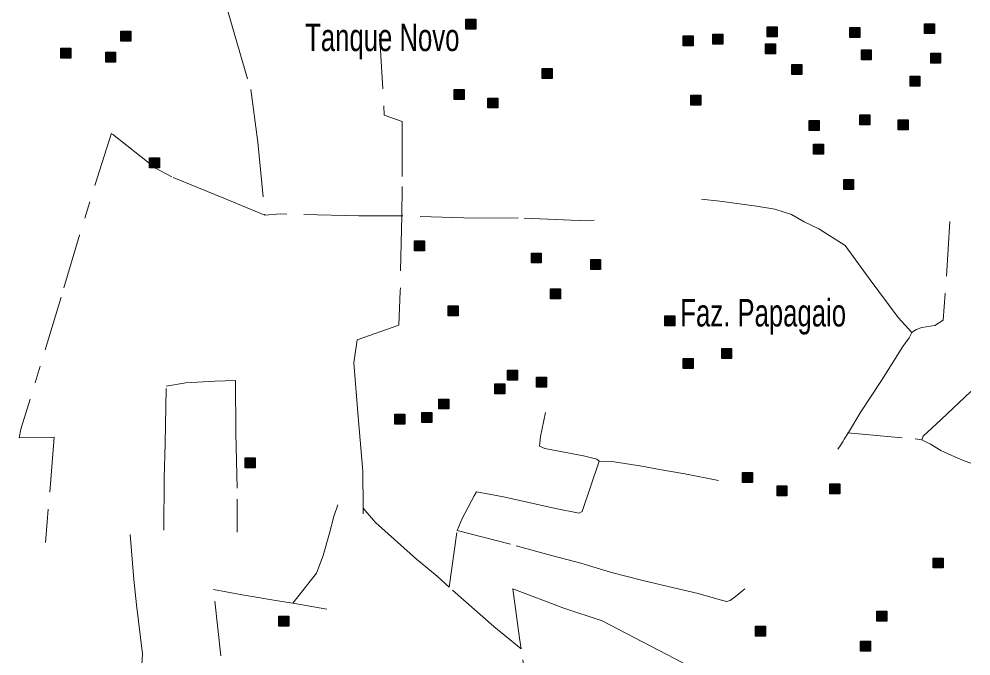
# Model space of a CAD drawing. Extents: x 445.4 to 500, y 8728.7 to 8784.
# Drawn here: x 494.45 to 500, y 8730.77 to 8734.48 of the extents above; entities that cross this region are included whole.
import ezdxf
from ezdxf.enums import TextEntityAlignment as Align

# ---------------------------------------------------------------- set-up
doc = ezdxf.new("R2010")
doc.units = 0
doc.header["$LTSCALE"] = 0.064
doc.linetypes.add('DOT_DASHED', pattern=[7.7, 5, -1.2, 0.3, -1.2])
doc.layers.add('2', color=7, linetype='Continuous', lineweight=25)
doc.layers.add('22', color=7, linetype='DOT_DASHED', lineweight=13)
doc.layers.add('61', color=7, linetype='Continuous')

msp = doc.modelspace()

# ---------------------------------------------------------------- hatches: boundary and pattern name
at = {"layer": '2'}
for points in [[(497.0563, 8734.475), (497.1143, 8734.475), (497.1143, 8734.417), (497.0563, 8734.417)], [(498.8131, 8734.4308), (498.8711, 8734.4308), (498.8711, 8734.3728), (498.8131, 8734.3728)], [(499.7287, 8734.449), (499.7867, 8734.449), (499.7867, 8734.391), (499.7287, 8734.391)], [(495.0456, 8734.4055), (495.1036, 8734.4055), (495.1036, 8734.3475), (495.0456, 8734.3475)], [(498.323, 8734.3781), (498.381, 8734.3781), (498.381, 8734.3201), (498.323, 8734.3201)], [(498.4961, 8734.3877), (498.5541, 8734.3877), (498.5541, 8734.3297), (498.4961, 8734.3297)], [(499.2946, 8734.4271), (499.3526, 8734.4271), (499.3526, 8734.3691), (499.2946, 8734.3691)], [(498.8021, 8734.3322), (498.8601, 8734.3322), (498.8601, 8734.2742), (498.8021, 8734.2742)], [(494.6956, 8734.3068), (494.7536, 8734.3068), (494.7536, 8734.2488), (494.6956, 8734.2488)], [(494.9569, 8734.2822), (495.0149, 8734.2822), (495.0149, 8734.2242), (494.9569, 8734.2242)], [(499.3612, 8734.2957), (499.4192, 8734.2957), (499.4192, 8734.2377), (499.3612, 8734.2377)], [(499.7652, 8734.2774), (499.8232, 8734.2774), (499.8232, 8734.2194), (499.7652, 8734.2194)], [(498.9553, 8734.2118), (499.0133, 8734.2118), (499.0133, 8734.1538), (498.9553, 8734.1538)], [(497.5004, 8734.1885), (497.5584, 8734.1885), (497.5584, 8734.1305), (497.5004, 8734.1305)], [(499.6448, 8734.1424), (499.7028, 8734.1424), (499.7028, 8734.0844), (499.6448, 8734.0844)], [(496.9878, 8734.0652), (497.0458, 8734.0652), (497.0458, 8734.0072), (496.9878, 8734.0072)], [(497.1849, 8734.0159), (497.2429, 8734.0159), (497.2429, 8733.9579), (497.1849, 8733.9579)], [(498.3679, 8734.0327), (498.4259, 8734.0327), (498.4259, 8733.9747), (498.3679, 8733.9747)], [(499.0575, 8733.8854), (499.1155, 8733.8854), (499.1155, 8733.8274), (499.0575, 8733.8274)], [(499.3529, 8733.9183), (499.4109, 8733.9183), (499.4109, 8733.8603), (499.3529, 8733.8603)], [(499.5755, 8733.8891), (499.6335, 8733.8891), (499.6335, 8733.8311), (499.5755, 8733.8311)], [(499.083, 8733.7477), (499.141, 8733.7477), (499.141, 8733.6897), (499.083, 8733.6897)], [(495.2132, 8733.6677), (495.2712, 8733.6677), (495.2712, 8733.6097), (495.2132, 8733.6097)], [(499.2581, 8733.5416), (499.3161, 8733.5416), (499.3161, 8733.4836), (499.2581, 8733.4836)], [(496.7561, 8733.1844), (496.8141, 8733.1844), (496.8141, 8733.1264), (496.7561, 8733.1264)], [(497.4378, 8733.1128), (497.4958, 8733.1128), (497.4958, 8733.0548), (497.4378, 8733.0548)], [(497.7836, 8733.0747), (497.8416, 8733.0747), (497.8416, 8733.0167), (497.7836, 8733.0167)], [(497.5497, 8732.9033), (497.6077, 8732.9033), (497.6077, 8732.8453), (497.5497, 8732.8453)], [(496.9532, 8732.8047), (497.0112, 8732.8047), (497.0112, 8732.7467), (496.9532, 8732.7467)], [(498.2167, 8732.7469), (498.2747, 8732.7469), (498.2747, 8732.6889), (498.2167, 8732.6889)], [(498.5472, 8732.5563), (498.6052, 8732.5563), (498.6052, 8732.4983), (498.5472, 8732.4983)], [(498.3236, 8732.4989), (498.3816, 8732.4989), (498.3816, 8732.4409), (498.3236, 8732.4409)], [(497.2983, 8732.4299), (497.3563, 8732.4299), (497.3563, 8732.3719), (497.2983, 8732.3719)], [(497.4682, 8732.3886), (497.5262, 8732.3886), (497.5262, 8732.3306), (497.4682, 8732.3306)], [(497.2244, 8732.3509), (497.2824, 8732.3509), (497.2824, 8732.2929), (497.2244, 8732.2929)], [(496.899, 8732.2622), (496.957, 8732.2622), (496.957, 8732.2042), (496.899, 8732.2042)], [(496.6427, 8732.1734), (496.7007, 8732.1734), (496.7007, 8732.1154), (496.6427, 8732.1154)], [(496.7994, 8732.1828), (496.8574, 8732.1828), (496.8574, 8732.1248), (496.7994, 8732.1248)], [(495.7702, 8731.919), (495.8282, 8731.919), (495.8282, 8731.861), (495.7702, 8731.861)], [(498.6686, 8731.8331), (498.7266, 8731.8331), (498.7266, 8731.7751), (498.6686, 8731.7751)], [(499.1779, 8731.7677), (499.2359, 8731.7677), (499.2359, 8731.7097), (499.1779, 8731.7097)], [(498.8698, 8731.7555), (498.9278, 8731.7555), (498.9278, 8731.6975), (498.8698, 8731.6975)], [(499.7797, 8731.3356), (499.8377, 8731.3356), (499.8377, 8731.2776), (499.7797, 8731.2776)], [(495.9668, 8730.9972), (496.0248, 8730.9972), (496.0248, 8730.9392), (495.9668, 8730.9392)], [(499.4514, 8731.0253), (499.5094, 8731.0253), (499.5094, 8730.9673), (499.4514, 8730.9673)], [(498.7438, 8730.9377), (498.8018, 8730.9377), (498.8018, 8730.8797), (498.7438, 8730.8797)], [(499.3566, 8730.8508), (499.4146, 8730.8508), (499.4146, 8730.7928), (499.3566, 8730.7928)]]:
    msp.add_hatch(color=256, dxfattribs=at).paths.add_polyline_path(points)

# ---------------------------------------------------------------- linework, layer by layer
for points in [[(497.0563, 8734.475), (497.1143, 8734.475), (497.1143, 8734.417), (497.0563, 8734.417)], [(498.8131, 8734.4308), (498.8711, 8734.4308), (498.8711, 8734.3728), (498.8131, 8734.3728)], [(499.7287, 8734.449), (499.7867, 8734.449), (499.7867, 8734.391), (499.7287, 8734.391)], [(495.0456, 8734.4055), (495.1036, 8734.4055), (495.1036, 8734.3475), (495.0456, 8734.3475)], [(498.323, 8734.3781), (498.381, 8734.3781), (498.381, 8734.3201), (498.323, 8734.3201)], [(498.4961, 8734.3877), (498.5541, 8734.3877), (498.5541, 8734.3297), (498.4961, 8734.3297)], [(499.2946, 8734.4271), (499.3526, 8734.4271), (499.3526, 8734.3691), (499.2946, 8734.3691)], [(498.8021, 8734.3322), (498.8601, 8734.3322), (498.8601, 8734.2742), (498.8021, 8734.2742)], [(494.6956, 8734.3068), (494.7536, 8734.3068), (494.7536, 8734.2488), (494.6956, 8734.2488)], [(494.9569, 8734.2822), (495.0149, 8734.2822), (495.0149, 8734.2242), (494.9569, 8734.2242)], [(499.3612, 8734.2957), (499.4192, 8734.2957), (499.4192, 8734.2377), (499.3612, 8734.2377)], [(499.7652, 8734.2774), (499.8232, 8734.2774), (499.8232, 8734.2194), (499.7652, 8734.2194)], [(498.9553, 8734.2118), (499.0133, 8734.2118), (499.0133, 8734.1538), (498.9553, 8734.1538)], [(497.5004, 8734.1885), (497.5584, 8734.1885), (497.5584, 8734.1305), (497.5004, 8734.1305)], [(499.6448, 8734.1424), (499.7028, 8734.1424), (499.7028, 8734.0844), (499.6448, 8734.0844)], [(496.9878, 8734.0652), (497.0458, 8734.0652), (497.0458, 8734.0072), (496.9878, 8734.0072)], [(497.1849, 8734.0159), (497.2429, 8734.0159), (497.2429, 8733.9579), (497.1849, 8733.9579)], [(498.3679, 8734.0327), (498.4259, 8734.0327), (498.4259, 8733.9747), (498.3679, 8733.9747)], [(499.0575, 8733.8854), (499.1155, 8733.8854), (499.1155, 8733.8274), (499.0575, 8733.8274)], [(499.3529, 8733.9183), (499.4109, 8733.9183), (499.4109, 8733.8603), (499.3529, 8733.8603)], [(499.5755, 8733.8891), (499.6335, 8733.8891), (499.6335, 8733.8311), (499.5755, 8733.8311)], [(499.083, 8733.7477), (499.141, 8733.7477), (499.141, 8733.6897), (499.083, 8733.6897)], [(495.2132, 8733.6677), (495.2712, 8733.6677), (495.2712, 8733.6097), (495.2132, 8733.6097)], [(499.2581, 8733.5416), (499.3161, 8733.5416), (499.3161, 8733.4836), (499.2581, 8733.4836)], [(496.7561, 8733.1844), (496.8141, 8733.1844), (496.8141, 8733.1264), (496.7561, 8733.1264)], [(497.4378, 8733.1128), (497.4958, 8733.1128), (497.4958, 8733.0548), (497.4378, 8733.0548)], [(497.7836, 8733.0747), (497.8416, 8733.0747), (497.8416, 8733.0167), (497.7836, 8733.0167)], [(497.5497, 8732.9033), (497.6077, 8732.9033), (497.6077, 8732.8453), (497.5497, 8732.8453)], [(496.9532, 8732.8047), (497.0112, 8732.8047), (497.0112, 8732.7467), (496.9532, 8732.7467)], [(498.2167, 8732.7469), (498.2747, 8732.7469), (498.2747, 8732.6889), (498.2167, 8732.6889)], [(498.5472, 8732.5563), (498.6052, 8732.5563), (498.6052, 8732.4983), (498.5472, 8732.4983)], [(498.3236, 8732.4989), (498.3816, 8732.4989), (498.3816, 8732.4409), (498.3236, 8732.4409)], [(497.2983, 8732.4299), (497.3563, 8732.4299), (497.3563, 8732.3719), (497.2983, 8732.3719)], [(497.4682, 8732.3886), (497.5262, 8732.3886), (497.5262, 8732.3306), (497.4682, 8732.3306)], [(497.2244, 8732.3509), (497.2824, 8732.3509), (497.2824, 8732.2929), (497.2244, 8732.2929)], [(496.899, 8732.2622), (496.957, 8732.2622), (496.957, 8732.2042), (496.899, 8732.2042)], [(496.6427, 8732.1734), (496.7007, 8732.1734), (496.7007, 8732.1154), (496.6427, 8732.1154)], [(496.7994, 8732.1828), (496.8574, 8732.1828), (496.8574, 8732.1248), (496.7994, 8732.1248)], [(495.7702, 8731.919), (495.8282, 8731.919), (495.8282, 8731.861), (495.7702, 8731.861)], [(498.6686, 8731.8331), (498.7266, 8731.8331), (498.7266, 8731.7751), (498.6686, 8731.7751)], [(499.1779, 8731.7677), (499.2359, 8731.7677), (499.2359, 8731.7097), (499.1779, 8731.7097)], [(498.8698, 8731.7555), (498.9278, 8731.7555), (498.9278, 8731.6975), (498.8698, 8731.6975)], [(499.7797, 8731.3356), (499.8377, 8731.3356), (499.8377, 8731.2776), (499.7797, 8731.2776)], [(495.9668, 8730.9972), (496.0248, 8730.9972), (496.0248, 8730.9392), (495.9668, 8730.9392)], [(499.4514, 8731.0253), (499.5094, 8731.0253), (499.5094, 8730.9673), (499.4514, 8730.9673)], [(498.7438, 8730.9377), (498.8018, 8730.9377), (498.8018, 8730.8797), (498.7438, 8730.8797)], [(499.3566, 8730.8508), (499.4146, 8730.8508), (499.4146, 8730.7928), (499.3566, 8730.7928)]]:
    msp.add_lwpolyline(points, close=True, dxfattribs=at)
at = {"layer": '22'}
for p, q in [((496.9596, 8731.1667), (497.0057, 8731.4966)), ((497.4368, 8730.4265), (497.3788, 8730.8058))]:
    msp.add_line(p, q, dxfattribs=at)
for points in [[(495.594, 8734.7512), (495.6264, 8734.6731), (495.6949, 8734.4352), (495.8021, 8734.0663), (495.8436, 8733.7581), (495.8853, 8733.3327)], [(496.5532, 8734.3898), (496.5802, 8733.9168), (496.6853, 8733.8793), (496.6853, 8733.5009), (496.6821, 8733.3293)], [(495.8853, 8733.3327), (495.6464, 8733.4318), (495.343, 8733.556), (495.248, 8733.6071), (494.9902, 8733.8111), (494.8034, 8733.2161), (494.6974, 8732.8546), (494.4633, 8732.0855), (494.4519, 8732.0356), (494.6567, 8732.0392), (494.6164, 8731.5463), (494.6052, 8731.4262)], [(499.1126, 8733.2543), (499.0272, 8733.2945), (498.9536, 8733.3366), (498.8568, 8733.3681), (498.7495, 8733.3849), (498.5366, 8733.414), (498.4297, 8733.4265)], [(496.6821, 8733.3293), (496.6738, 8733.3296), (496.4325, 8733.3296), (495.9755, 8733.3406), (495.8853, 8733.3327)], [(496.6821, 8733.3293), (496.6739, 8732.8908), (496.6664, 8732.6921), (496.4225, 8732.606), (496.4028, 8732.4722), (496.4291, 8732.1575), (496.4554, 8731.8427), (496.4568, 8731.6262), (496.457, 8731.5925)], [(497.803, 8733.3051), (497.7163, 8733.3027), (497.3605, 8733.318), (497.1088, 8733.315), (496.6821, 8733.3293)], [(499.8771, 8733.2972), (499.8505, 8732.8768), (499.8385, 8732.7212), (499.7888, 8732.691), (499.7135, 8732.6797), (499.6816, 8732.668), (499.6554, 8732.6496)], [(499.1126, 8733.2543), (499.2672, 8733.156), (499.4071, 8732.9645), (499.5748, 8732.7371), (499.6554, 8732.6496)], [(499.6554, 8732.6496), (499.6393, 8732.6192), (499.6034, 8732.5674), (499.479, 8732.3701), (499.3591, 8732.1866), (499.2863, 8732.0666)], [(495.2959, 8731.4974), (495.2987, 8731.8009), (495.304, 8732.0038), (495.3094, 8732.3375), (495.4243, 8732.3562), (495.5927, 8732.3669), (495.713, 8732.3695), (495.7157, 8732.0625), (495.7237, 8731.6781), (495.7236, 8731.4854)], [(499.7139, 8732.0234), (499.722, 8732.0464), (499.8262, 8732.1437), (500, 8732.3067)], [(497.8335, 8731.9007), (497.8335, 8731.9007), (497.8194, 8731.9124), (497.7418, 8731.9312), (497.5161, 8731.9735), (497.4855, 8731.9876), (497.4902, 8732.0439), (497.5198, 8732.1842)], [(499.2863, 8732.0666), (499.2613, 8732.0273), (499.2545, 8732.0167), (499.2409, 8731.9948), (499.2244, 8731.9697)], [(499.2795, 8732.0647), (499.6744, 8732.03), (499.7139, 8732.0234)], [(499.7139, 8732.0234), (499.7639, 8731.9983), (499.8241, 8731.963), (499.9067, 8731.9252), (499.9609, 8731.9011), (500, 8731.8883)], [(497.0057, 8731.4966), (497.0343, 8731.5654), (497.1036, 8731.6978), (497.1182, 8731.7221), (497.276, 8731.6928), (497.578, 8731.6247), (497.716, 8731.5977), (497.7348, 8731.6071), (497.8335, 8731.9007)], [(497.8335, 8731.9007), (497.9197, 8731.8967), (498.0818, 8731.8713), (498.1838, 8731.8513), (498.3331, 8731.8258), (498.5285, 8731.7866)], [(496.0473, 8731.072), (496.1855, 8731.2466), (496.2251, 8731.3503), (496.262, 8731.48), (496.2866, 8731.5769), (496.3104, 8731.6453)], [(496.9596, 8731.1667), (496.8881, 8731.2308), (496.7675, 8731.3281), (496.5288, 8731.5421), (496.4568, 8731.6262)], [(497.0057, 8731.4966), (497.35, 8731.407), (497.5548, 8731.3512), (497.7254, 8731.3048), (497.9054, 8731.2521), (498.0884, 8731.2056)], [(494.5393, 8730.5022), (494.5423, 8730.5031), (494.6872, 8730.5221), (494.8016, 8730.5374), (494.9008, 8730.5754), (495.1677, 8730.7125), (495.1715, 8730.7773), (495.1372, 8731.0629), (495.1219, 8731.2114), (495.1004, 8731.472)], [(497.3788, 8730.8058), (497.2182, 8730.9365), (496.9596, 8731.1667)], [(498.0884, 8731.2056), (498.2683, 8731.1615), (498.4095, 8731.1287), (498.5249, 8731.0959), (498.5746, 8731.0829), (498.5965, 8731.0879), (498.6353, 8731.1177), (498.6821, 8731.1564)], [(495.6287, 8730.7656), (495.5848, 8731.1516), (495.753, 8731.1205), (495.9833, 8731.0832), (496.0473, 8731.072), (496.2452, 8731.0374)], [(497.3788, 8730.8058), (497.3692, 8730.8684), (497.3302, 8731.1554), (497.6274, 8731.0435), (497.8514, 8730.9705), (498.0365, 8730.8732), (498.3239, 8730.7224), (498.6649, 8730.5424)]]:
    msp.add_lwpolyline(points, dxfattribs=at)

# ---------------------------------------------------------------- texts
at = {"layer": '61', "width": 0.7}
msp.add_text('Tanque Novo', height=0.16, dxfattribs=at).set_placement((497.0187, 8734.2893), align=Align.RIGHT)
msp.add_text('Faz. Papagaio', height=0.16, dxfattribs=at).set_placement((498.3061, 8732.6848))

doc.saveas('drawing.dxf')
